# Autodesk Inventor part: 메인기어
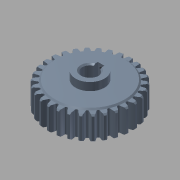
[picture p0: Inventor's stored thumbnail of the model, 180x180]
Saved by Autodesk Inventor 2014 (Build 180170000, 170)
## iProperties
Created: 2011-08
Part Number: 메인기어
Document SubType Name: Modeling
Designer: KYOUNG IL JANG
Density: 7.86 g/cm^3
Material: 강철, 연강
Mass: 423.557 g
Surface Area: 135.188 cm^2
Volume: 53.8877 cm^3
Description: 잇수:30 / PCD:60
Appearance: 강청색
Author: mm
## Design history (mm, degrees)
sketch "스케치1"
  geometry: C1 r 27.5 at (0, 0); A1 r 27.5 centre (0, 0) between (2.757, 27.361) and (-2.757, 27.361); A2 r 32 centre (0, 0) between (0.737, 31.992) and (-0.737, 31.992); A3 r 1.004 centre (-2.903, 28.355) between (-2.757, 27.361) and (-1.899, 28.332); A4 r 7.498 centre (5.568, 27.656) between (-1.648, 29.691) and (-1.899, 28.332); A5 r 12.465 centre (10.34, 26.276) between (-0.737, 31.992) and (-1.648, 29.691); A6 r 1.004 centre (2.903, 28.355) between (1.899, 28.332) and (2.757, 27.361); A7 r 7.498 centre (-5.568, 27.656) between (1.899, 28.332) and (1.648, 29.691); A8 r 12.465 centre (-10.34, 26.276) between (1.648, 29.691) and (0.737, 31.992); 1 further point
  constraints: 16 point on circle, 9 centre point, 1 coincident, 1 concentric
extrude "돌출1" new body sketch "스케치1" stored distance "d0" = 20; taper "d1" = 0 deg
extrude "돌출2" join sketch "스케치1" stored distance "d2" = 18; taper "d3" = 0 deg
chamfer "모따기1" distance "d4" = 1; stored, may be unused: second distance "d5" = 2, angle "d6" = 45 deg
sketch "스케치2"
  geometry: 1 further point
hole "구멍1" sketch "스케치2" at (0, 0) diameter "d10" = 12; stored, may be unused: countersink angle "d14" = 90 deg, drill point angle "d16" = 118 deg; dims "d11" = 6, "d12" = 4, "d13" = 2, "d15" = 8
sketch "스케치3"
  geometry: L1 (-2.5, 5.454)-(-2.5, 8.5); L2 (-2.5, 8.5)-(2.5, 8.5); L3 (2.5, 8.5)-(2.5, 5.454); C1 r 6 at (0, 0); A1 r 6 centre (0, 0) between (-2.5, 5.454) and (2.5, 5.454) reference; 1 further point
  constraints: 6 end point, 2 point on circle, 2 vertical, 1 centre point, 1 coincident, 1 horizontal, 1 parallel
  dimensions: "d17" = 2.5 distance edge to line of A1 L2; "d18" = 5 distance of L1.end L2.end; "d27" = 12 diameter of C1
extrude "돌출3" cut sketch "스케치3" stored distance "d19" = 10; taper "d20" = 0 deg
chamfer "모따기2" distance "d21" = 1; stored, may be unused: second distance "d22" = 2, angle "d23" = 45 deg
chamfer "모따기3" distance "d24" = 1; stored, may be unused: second distance "d25" = 2, angle "d26" = 45 deg
sketch "스케치4"
  geometry: L1 (2.5, 8.5)-(2.5, 5.454) reference; L2 (-2.5, 8.5)-(2.5, 8.5) reference; L3 (-2.5, 5.454)-(-2.5, 8.5) reference; C1 r 11 at (0, 0); A1 r 6 centre (0, 0) between (-2.5, 5.454) and (2.5, 5.454) reference; 1 further point
  constraints: 1 centre point, 1 coincident
  dimensions: "d28" = 22 diameter of C1
extrude "돌출4" join sketch "스케치4" distance "d30" = 6; taper "d31" = 0 deg
chamfer "모따기4" distance "d40" = 1; stored, may be unused: second distance "d41" = 2, angle "d42" = 45 deg
node "작업 평면1"
sketch "스케치5"
  geometry: L1 (11, 6)-(-11, 6) reference; 2 further points
  constraints: 1 vertical alignment
  dimensions: "d32" = 3 distance from line of point (0, 3) L1
hole "구멍2" sketch "스케치5" at (0, 3) diameter "d33" = 2.459; stored, may be unused: countersink angle "d37" = 90 deg, drill point angle "d39" = 118 deg; dims "d34" = 6, "d35" = 4, "d36" = 2, "d38" = 8
node "솔리드1"
pattern_circular "원형 패턴1" dims angle "d8" = 360 deg
